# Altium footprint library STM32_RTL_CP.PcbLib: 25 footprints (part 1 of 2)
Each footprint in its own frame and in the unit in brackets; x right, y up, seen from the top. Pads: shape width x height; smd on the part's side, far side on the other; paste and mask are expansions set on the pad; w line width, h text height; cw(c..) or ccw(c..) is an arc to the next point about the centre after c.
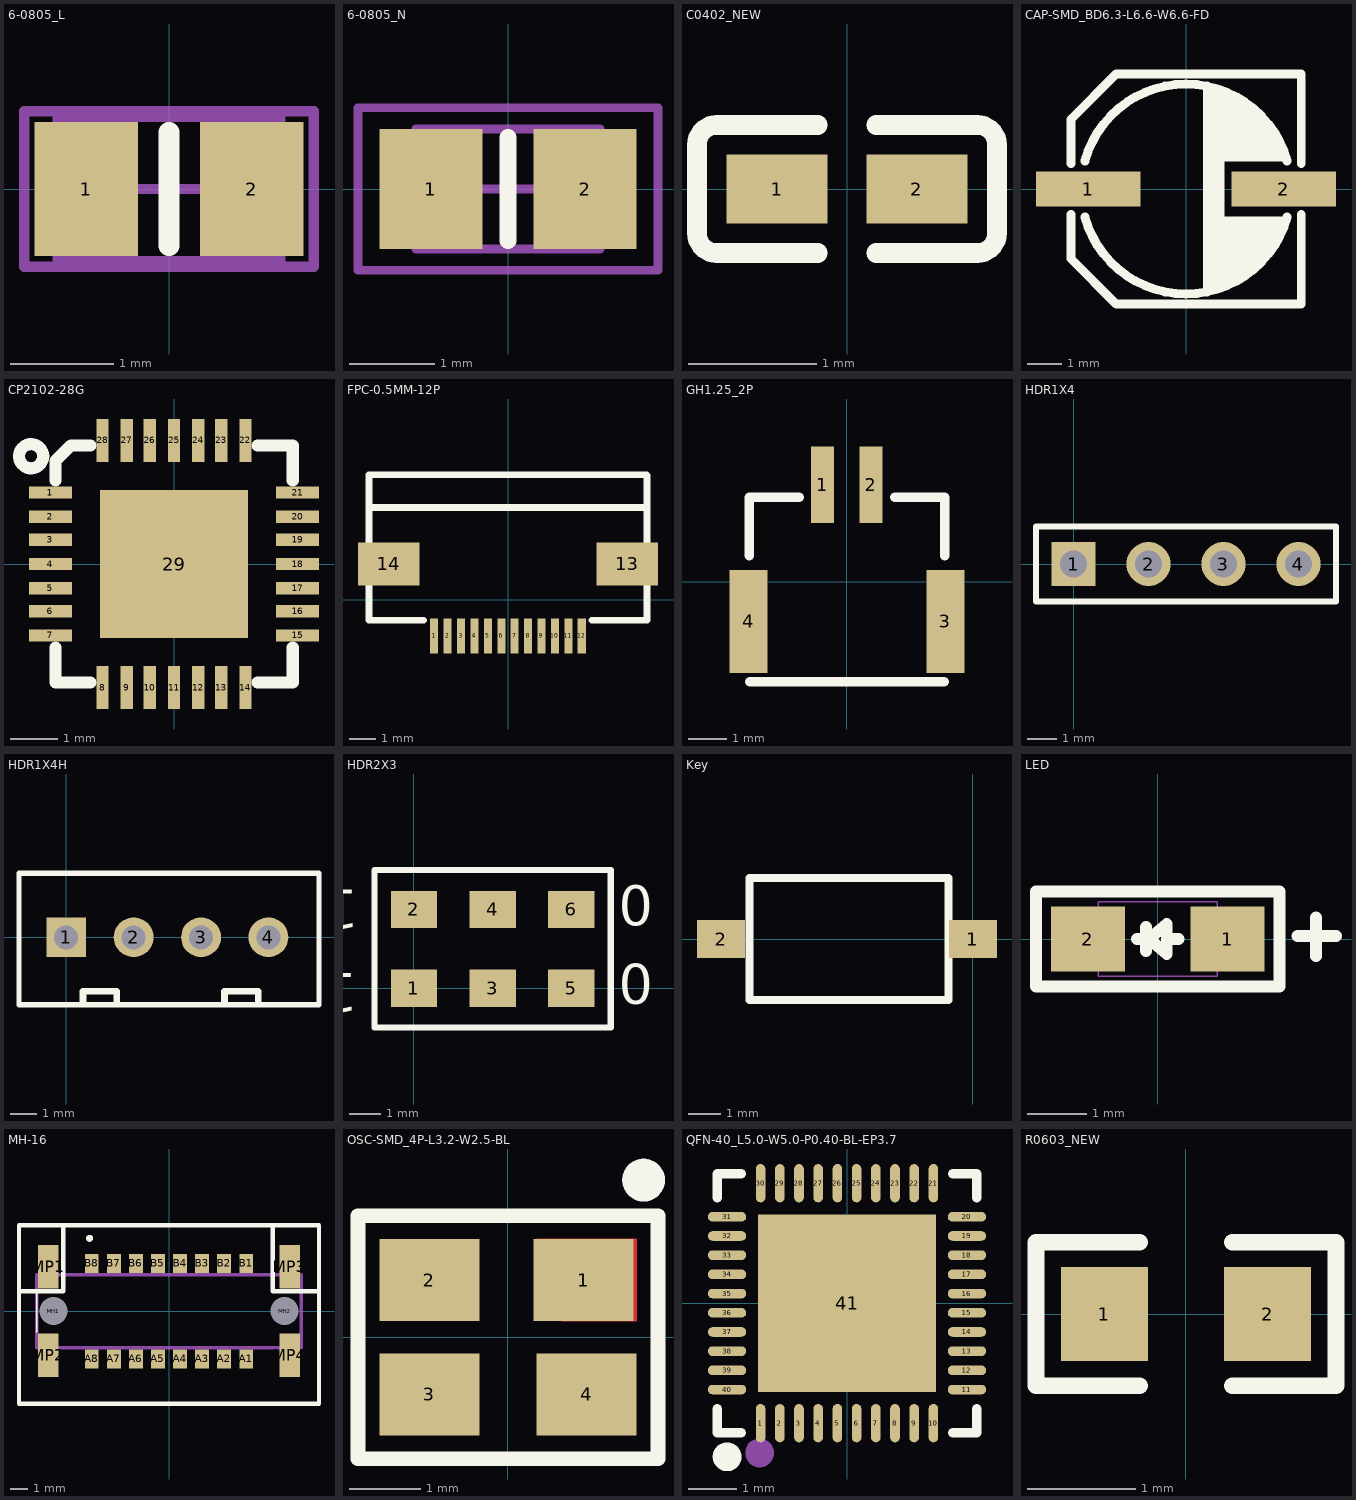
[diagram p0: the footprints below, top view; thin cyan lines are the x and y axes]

## 6-0805_L [mm] "Chip Resistor, Body 2.0x1.2mm, IPC High Density"
height 0.7
pads (2):
  rect 1x1.3 smd: 1(-0.8,0) 2(0.8,0)
Top Overlay:
  lines w0.2: 0,-0.55 0,0.55
Mechanical 13:
  lines w0.1: -1.075,-0.7 -1.075,0.7 1.075,0.7 1.075,-0.7 -1.075,-0.7
Mechanical 15:
  lines w0.1: -0.5,0 0.5,0 ; 0,-0.5 0,0.5 ; -1.4,-0.75 -1.4,0.75 1.4,0.75 1.4,-0.75 -1.4,-0.75
3D body: height 0.7, standoff 0, extent -1.075,-0.7 1.075,0.7

## 6-0805_N [mm] "Chip Resistor, Body 2.0x1.2mm, IPC Medium Density"
height 0.7
pads (2):
  rect 1.2x1.4 smd: 1(-0.9,0) 2(0.9,0)
Top Overlay:
  lines w0.2: 0,-0.6 0,0.6
Mechanical 13:
  lines w0.1: -1.075,-0.7 -1.075,0.7 1.075,0.7 1.075,-0.7 -1.075,-0.7
Mechanical 15:
  lines w0.1: -0.5,0 0.5,0 ; 0,-0.5 0,0.5 ; -1.75,-0.95 -1.75,0.95 1.75,0.95 1.75,-0.95 -1.75,-0.95
3D body: height 0.7, standoff 0, extent -1.075,-0.7 1.075,0.7

## C0402_NEW [mm]
pads (2):
  rect 0.79x0.54 smd: 1(-0.545,0) 2(0.545,0)
Top Overlay:
  lines w0.152: -0.226,-0.499 -1.016,-0.499 cw(c-1.016,-0.346) -1.169,-0.346 -1.169,0.346 cw(c-1.016,0.346) -1.016,0.499 -0.226,0.499 ; 0.226,-0.499 1.016,-0.499 ccw(c1.016,-0.346) 1.169,-0.346 1.169,0.346 ccw(c1.016,0.346) 1.016,0.499 0.226,0.499
Top Paste:
  region: 0.83,0.225 0.83,-0.225 0.78,-0.275 0.25,-0.275 0.2,-0.225 0.2,0.225 0.25,0.275 0.78,0.275
  region: -0.2,0.225 -0.2,-0.225 -0.25,-0.275 -0.78,-0.275 -0.83,-0.225 -0.83,0.225 -0.78,0.275 -0.25,0.275

## CAP-SMD_BD6.3-L6.6-W6.6-FD [mm]
pads (2):
  rect 3x1 smd: 1(-2.8,0) 2(2.8,0)
Top Overlay:
  region: 0.5,-3 0.5,2.9 0.5,3 0.5,2.9 1.1,2.8 1.6,2.6 1.9,2.3 2.2,2.1 2.5,1.8 2.7,1.4 2.9,0.8 1.1,0.8 1.1,-0.8 2.9,-0.8 2.8,-1 2.7,-1.4 2.4,-1.7 2.2,-2.1 1.8,-2.4 1.4,-2.6 1,-2.8
  lines w0.254: -3.297,-0.732 -3.297,-1.999 -1.996,-3.299 3.302,-3.299 3.302,-0.732 ; -3.297,0.732 -3.297,1.999 -1.996,3.299 3.302,3.299 3.302,0.732 ; -2.9,-0.8 ccw(c0,0) 2.9,-0.8 ; -2.9,0.8 cw(c0,0) 2.9,0.8

## CP2102-28G [mil]
pads (29):
  rect 35.4x10 smd: 1(-102,59) 2(-102,39) 3(-102,20) 4(-102,0) 5(-102,-20) 6(-102,-39) 7(-102,-59) 15(102,-59) 16(102,-39) 17(102,-20) 18(102,0) 19(102,20) 20(102,39) 21(102,59)
  rect 10x35.4 smd: 8(-59,-102) 9(-39,-102) 10(-20,-102) 11(0,-102) 12(20,-102) 13(39,-102) 14(59,-102) 22(59,102) 23(39,102) 24(20,102) 25(0,102) 26(-20,102) 27(-39,102) 28(-59,102)
  rect 122x122 smd: 29(0,0)
Top Overlay:
  circle w10: c-118,89 r10
  lines w10: -98,-69 -98,-98 -69,-98 ; -98,69 -98,85 -85,98 -69,98 ; 69,-98 98,-98 98,-69 ; 69,98 98,98 98,69

## FPC-0.5MM-12P [mm]
pads (14):
  rect 0.3x1.3 smd: 1(-2.751,-1.341) 2(-2.252,-1.341) 3(-1.751,-1.341) 4(-1.251,-1.341) 5(-0.751,-1.341) 6(-0.25,-1.341) 7(0.25,-1.341) 8(0.749,-1.341) 9(1.248,-1.341) 10(1.749,-1.341) 11(2.249,-1.341) 12(2.75,-1.341)
  rect 2.286x1.6 smd: 13(4.45,1.34) 14(-4.45,1.34)
Top Overlay:
  lines w0.254: -5.18,-0.76 -5.18,3.433 -5.18,4.65 ; -5.18,3.45 5.18,3.45 ; -5.18,4.67 5.16,4.67 ; -5.17,-0.76 -3.15,-0.76 ; 3.13,-0.76 5.18,-0.76 ; 5.18,-0.76 5.18,4.65

## GH1.25_2P [mm]
pads (4):
  rect 0.6x2 smd: 1(-0.635,2.54) 2(0.635,2.54)
  rect 1x2.7 smd: 3(2.585,-1.041) 4(-2.565,-1.041)
Top Overlay:
  lines w0.254: -2.55,0.686 -2.55,2.21 -1.242,2.21 ; -2.53,-2.616 2.55,-2.616 ; 1.262,2.21 2.57,2.21 2.57,0.686

## HDR1X4 [mm] "Connector; Header; 4 Position"
pads (4):
  rect 1.5x1.5 hole 0.9: 1(0,0)
  round 1.5 hole 0.9: 2(2.54,0) 3(5.08,0) 4(7.62,0)
Top Overlay:
  lines w0.2: -1.27,-1.27 8.89,-1.27 8.89,1.27 -1.27,1.27 -1.27,-1.27

## HDR1X4H [mm] "Connector; Header; 4 Position; Right Angle"
pads (4):
  rect 1.5x1.5 hole 0.9: 1(0,0)
  round 1.5 hole 0.9: 2(2.54,0) 3(5.08,0) 4(7.62,0)
Top Overlay:
  lines w0.2: -1.778,-2.54 -1.778,2.413 9.525,2.413 9.525,-2.54 -1.778,-2.54
  lines w0.254: 0.635,-2.476 0.635,-2.032 1.905,-2.032 1.905,-2.476 ; 5.969,-2.413 5.969,-2.032 7.239,-2.032 7.239,-2.413

## HDR2X3 [mm] "Connector; Header; 3x2 Position"
height 4.32
pads (6):
  rect 1.5x1.2 smd: 1(0,0) 2(0,2.54) 3(2.54,0) 4(2.54,2.54) 5(5.08,0) 6(5.08,2.54)
Top Overlay:
  lines w0.2: 1.482,-1.27 6.35,-1.27 ; 6.35,-1.27 -1.27,-1.27 -1.27,3.81 6.35,3.81 6.35,-1.27
  text "1" at -1.807,0.486 h1.27
  text "1" at -1.778,3.175 h1.27
  text "0" at 6.604,-0.508 h1.27
  text "0" at 6.604,2.032 h1.27

## Key [mil]
pads (2):
  rect 59.06x47.24 smd: 1(0,0) 2(-310,0)
Top Overlay:
  lines w10: -275,-75 -275,75 -30,75 -30,-75 -275,-75

## LED [mil]
height 170.08
pads (2):
  rect 49x43 smd: 1(46.26,0) 2(-46.26,0)
Top Overlay:
  lines w7.87: -13.78,0 -5.91,0 ; -7.87,-7.87 -7.87,7.87 ; 5.91,0 13.78,0 ; 92.52,1.97 118.11,1.97 ; 104.75,-11.44 104.75,14.15 ; -5.91,0 5.91,9.84 5.91,-9.84 -5.91,0 ; -80.71,-31.5 80.71,-31.5 80.71,31.5 -80.71,31.5 -80.71,-31.5
Mechanical 8:
  lines w1: -39.37,-24.61 39.37,-24.61 39.37,24.61 -39.37,24.61 -39.37,-24.61

## MH-16 [mm]
pads (22):
  rect 0.8x1.1 smd: A1(4.445,-2.75) A2(3.175,-2.75) A3(1.905,-2.75) A4(0.635,-2.75) A5(-0.635,-2.75) A6(-1.905,-2.75) A7(-3.175,-2.75) A8(-4.445,-2.75) B1(4.445,2.75) B2(3.175,2.75) B3(1.905,2.75) B4(0.635,2.75) B5(-0.635,2.75) B6(-1.905,2.75) B7(-3.175,2.75) B8(-4.445,2.75)
  round 0.8 hole 1.6 unplated: MH1(-6.655,0) MH2(6.655,0)
  rect 1.2x2.5 smd: MP1(-6.955,2.55) MP2(-6.955,-2.55) MP3(6.955,2.55) MP4(6.955,-2.55)
Top Overlay:
  lines w0.013: -8.636,4.953 8.636,4.953
  lines w0.1: -7.62,-1.2 -7.62,1.1
  lines w0.2: -4.672,4.191 ccw(c-4.572,4.191) -4.472,4.191 ccw(c-4.572,4.191) -4.672,4.191
  lines w0.254: -8.636,1.143 -6.096,1.143 -6.096,4.953 ; 5.969,4.953 5.969,1.143 8.636,1.143 ; -8.636,-5.334 8.636,-5.334 8.636,4.953 -8.636,4.953 -8.636,-5.334
Mechanical 13:
  lines w0.2: -7.62,-2.1 7.62,-2.1 7.62,2.1 -7.62,2.1 -7.62,-2.1
Mechanical 15:
  lines w0.1: -8.62,-5.3 8.62,-5.3 8.62,5 -8.62,5 -8.62,-5.3
3D body "254587.stp": height 6.7, standoff -0.8, extent -7.62,-3.5 7.62,3.5

## OSC-SMD_4P-L3.2-W2.5-BL [mm]
pads (4):
  rect 1.4x1.15 smd: 1(1.059,0.8) 2(-1.1,0.8) 3(-1.1,-0.8) 4(1.1,-0.8)
Top Layer:
  region: 1.8,0.225 0.762,0.225 0.4,0.604 0.4,1.375 1.8,1.375
Top Overlay:
  lines w0.203: -2.1,-1.7 -2.1,1.7 2.1,1.7 2.1,-1.7 -2.1,-1.7
  lines w0.3: 1.897,2.05 cw(c1.899,2.2) 1.9,2.05
Top Paste:
  region: 1.8,0.225 0.762,0.225 0.4,0.604 0.4,1.375 1.8,1.375
Top Solder:
  region: 1.8,0.225 0.762,0.225 0.4,0.604 0.4,1.375 1.8,1.375

## QFN-40_L5.0-W5.0-P0.40-BL-EP3.7 [mm]
pads (41):
  oval 0.2x0.8 smd: 1(-1.8,-2.499) 2(-1.4,-2.499) 3(-1,-2.499) 4(-0.6,-2.499) 5(-0.2,-2.499) 6(0.2,-2.499) 7(0.6,-2.499) 8(1,-2.499) 9(1.4,-2.499) 10(1.8,-2.499) 21(1.8,2.499) 22(1.4,2.499) 23(1,2.499) 24(0.6,2.499) 25(0.2,2.499) 26(-0.2,2.499) 27(-0.6,2.499) 28(-1,2.499) 29(-1.4,2.499) 30(-1.8,2.499)
  oval 0.8x0.2 smd: 11(2.499,-1.8) 12(2.499,-1.4) 13(2.499,-1) 14(2.499,-0.6) 15(2.499,-0.2) 16(2.499,0.2) 17(2.499,0.6) 18(2.499,1) 19(2.499,1.4) 20(2.499,1.8) 31(-2.499,1.8) 32(-2.499,1.4) 33(-2.499,1) 34(-2.499,0.6) 35(-2.499,0.2) 36(-2.499,-0.2) 37(-2.499,-0.6) 38(-2.499,-1) 39(-2.499,-1.4) 40(-2.499,-1.8)
  rect 3.7x3.7 smd: 41(0,0)
Top Overlay:
  lines w0.2: -2.7,-2.2 -2.7,-2.7 -2.2,-2.7 ; -2.7,2.2 -2.7,2.7 -2.2,2.7 ; 2.2,-2.7 2.7,-2.7 2.7,-2.2 ; 2.2,2.7 2.7,2.7 2.7,2.2
  lines w0.3: -2.499,-3.051 ccw(c-2.498,-3.201) -2.497,-3.051
Mechanical 15:
  circle w0.3: c-1.82,-3.12 r0.15

## R0603_NEW [mm]
pads (2):
  rect 0.806x0.864 smd: 1(-0.753,0) 2(0.753,0)
Top Overlay:
  lines w0.152: -0.426,-0.661 -1.385,-0.661 -1.385,0.661 -0.426,0.661 ; 0.426,-0.661 1.385,-0.661 1.385,0.661 0.426,0.661
Top Paste:
  region: 1.3,0.45 0.45,0.45 0.4,0.4 0.4,0.15 0.7,0.15 0.7,-0.15 0.4,-0.15 0.4,-0.4 0.45,-0.45 1.3,-0.45 1.35,-0.4 1.35,0.4
  region: -0.4,0.4 -0.4,0.15 -0.7,0.15 -0.7,-0.15 -0.4,-0.15 -0.4,-0.4 -0.45,-0.45 -1.3,-0.45 -1.35,-0.4 -1.35,0.4 -1.3,0.45 -0.45,0.45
